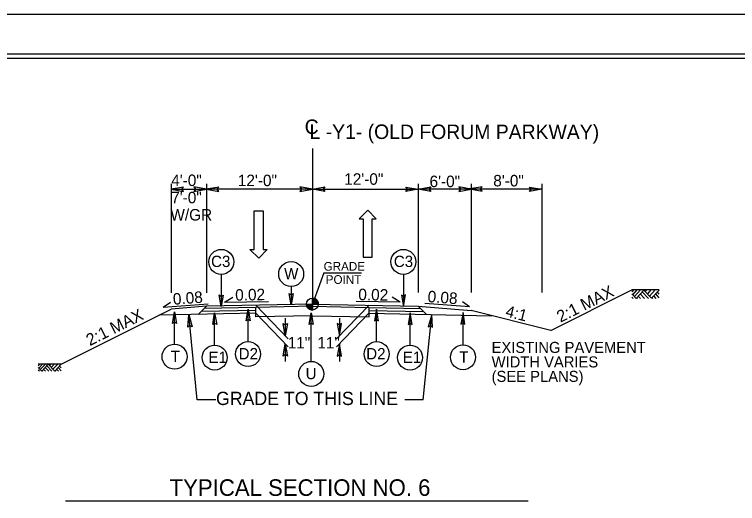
# Model space of a CAD drawing. Extents: x 1904401 to 1905163, y 193929 to 194736.
# Drawn here: x 1904832.2 to 1904914.1, y 194419 to 194474.3 of the extents above; entities that cross this region are included whole.
import ezdxf

# ---------------------------------------------------------------- set-up
doc = ezdxf.new("R2010")
doc.units = 0
for name, color, linetype in [('Old_Level_1', 7, 'Continuous'), ('Old_Level_11', 7, 'Continuous'), ('Old_Level_20', 7, 'Continuous'), ('Old_Level_3', 7, 'Continuous'), ('Prop Dimension Text', 7, 'Continuous'), ('Prop Lane Arrow CELL', 7, 'Continuous'), ('Sheet Cutting Line CELL', 7, 'Continuous'), ('Sheet Plot Border Inside CELL', 7, 'Continuous'), ('Sheet Plot Border Outside CELL', 7, 'Continuous'), ('Sheet Typical CELL', 7, 'Continuous'), ('Typical Arrow Superelevation CELL', 7, 'Continuous'), ('Typical Berm CELL', 7, 'Continuous'), ('Typical Hinge Slope Arterial CELL', 7, 'Continuous'), ('Typical Hinge Slope Interstate CELL', 7, 'Continuous'), ('Typical Terminator CELL', 7, 'Continuous'), ('Typical Text Centerline CELL', 7, 'Continuous')]:
    doc.layers.add(name, color=color, linetype=linetype)

# ---------------------------------------------------------------- blocks, each defined once
blk = doc.blocks.new('TERMINATOR')
at = {"layer": 'Typical Terminator CELL'}
blk.add_lwpolyline([(-0.469, 0.081), (0, 0), (-0.471, -0.083), (-0.411, 0)], close=True, dxfattribs=at)

msp = doc.modelspace()

# ---------------------------------------------------------------- linework, layer by layer
at = {"layer": 'Old_Level_1'}
for p, q in [((1904865.274, 194441.55), (1904865.949, 194441.55)), ((1904865.948, 194440.875), (1904865.949, 194441.55)), ((1904865.949, 194441.55), (1904865.948, 194440.875)), ((1904865.949, 194441.55), (1904865.949, 194442.225)), ((1904866.624, 194441.55), (1904865.949, 194441.55)), ((1904859.529, 194441.422), (1904863.203, 194437.626)), ((1904872.37, 194441.422), (1904868.696, 194437.626)), ((1904859.547, 194440.505), (1904863.203, 194436.729)), ((1904862.887, 194439.952), (1904862.887, 194437.952)), ((1904872.352, 194440.505), (1904868.696, 194436.729)), ((1904869.012, 194439.952), (1904869.012, 194437.952)), ((1904862.882, 194437.06), (1904862.882, 194435.06)), ((1904869.017, 194437.06), (1904869.017, 194435.06)), ((1904835.067, 194434.751), (1904834.897, 194434.567)), ((1904835.301, 194433.954), (1904834.897, 194434.389)), ((1904835.387, 194434.75), (1904834.973, 194434.306)), ((1904835.72, 194434.751), (1904835.14, 194434.128)), ((1904836.042, 194434.749), (1904835.301, 194433.954)), ((1904835.727, 194433.946), (1904835.51, 194434.178)), ((1904836.093, 194433.946), (1904835.693, 194434.374)), ((1904836.463, 194433.946), (1904835.877, 194434.574)), ((1904836.773, 194433.963), (1904836.042, 194434.749)), ((1904836.306, 194434.75), (1904836.173, 194434.608)), ((1904836.707, 194434.75), (1904836.375, 194434.391)), ((1904837.106, 194434.751), (1904836.573, 194434.177)), ((1904837.497, 194434.742), (1904836.773, 194433.963)), ((1904837.209, 194433.946), (1904836.982, 194434.189)), ((1904837.497, 194434.008), (1904837.155, 194434.374)), ((1904837.497, 194434.341), (1904837.311, 194434.541)), ((1904835.031, 194433.946), (1904834.897, 194434.089)), ((1904835.432, 194433.946), (1904835.363, 194434.019)), ((1904836.898, 194433.945), (1904836.827, 194434.021)), ((1904837.991, 194419.297), (1904890.384, 194419.297))]:
    msp.add_line(p, q, dxfattribs=at)
for points in [[(1904865.277, 194441.55), (1904865.277, 194441.477)], [(1904865.291, 194441.55), (1904865.291, 194441.397)], [(1904865.304, 194441.55), (1904865.304, 194441.349)], [(1904865.318, 194441.55), (1904865.318, 194441.309)], [(1904865.331, 194441.55), (1904865.331, 194441.277)], [(1904865.345, 194441.55), (1904865.345, 194441.249)], [(1904865.358, 194441.55), (1904865.358, 194441.223)], [(1904865.372, 194441.55), (1904865.372, 194441.199)], [(1904865.385, 194441.55), (1904865.385, 194441.178)], [(1904865.399, 194441.55), (1904865.399, 194441.159)], [(1904865.412, 194441.55), (1904865.412, 194441.141)], [(1904865.426, 194441.55), (1904865.426, 194441.124)], [(1904865.439, 194441.55), (1904865.439, 194441.108)], [(1904865.453, 194441.55), (1904865.453, 194441.093)], [(1904865.466, 194441.55), (1904865.466, 194441.078)], [(1904865.48, 194441.55), (1904865.48, 194441.064)], [(1904865.493, 194441.55), (1904865.493, 194441.052)], [(1904865.507, 194441.55), (1904865.507, 194441.04)], [(1904865.52, 194441.55), (1904865.52, 194441.028)], [(1904865.534, 194441.55), (1904865.534, 194441.018)], [(1904865.547, 194441.55), (1904865.547, 194441.007)], [(1904865.561, 194441.55), (1904865.561, 194440.998)], [(1904865.574, 194441.55), (1904865.574, 194440.989)], [(1904865.588, 194441.55), (1904865.588, 194440.98)], [(1904865.601, 194441.55), (1904865.601, 194440.971)], [(1904865.615, 194441.55), (1904865.615, 194440.964)], [(1904865.628, 194441.55), (1904865.628, 194440.956)], [(1904865.642, 194441.55), (1904865.642, 194440.949)], [(1904865.655, 194441.55), (1904865.655, 194440.943)], [(1904865.669, 194441.55), (1904865.669, 194440.937)], [(1904865.682, 194441.55), (1904865.682, 194440.931)], [(1904865.696, 194441.55), (1904865.696, 194440.925)], [(1904865.709, 194441.55), (1904865.709, 194440.919)], [(1904865.723, 194441.55), (1904865.723, 194440.914)], [(1904865.736, 194441.55), (1904865.736, 194440.91)], [(1904865.75, 194441.55), (1904865.75, 194440.905)], [(1904865.763, 194441.55), (1904865.763, 194440.902)], [(1904865.777, 194441.55), (1904865.777, 194440.898)], [(1904865.79, 194441.55), (1904865.79, 194440.895)], [(1904865.804, 194441.55), (1904865.804, 194440.892)], [(1904865.817, 194441.55), (1904865.817, 194440.889)], [(1904865.831, 194441.55), (1904865.831, 194440.886)], [(1904865.844, 194441.55), (1904865.844, 194440.884)], [(1904865.858, 194441.55), (1904865.858, 194440.881)], [(1904865.871, 194441.55), (1904865.871, 194440.88)], [(1904865.885, 194441.55), (1904865.885, 194440.878)], [(1904865.898, 194441.55), (1904865.898, 194440.877)], [(1904865.912, 194441.55), (1904865.912, 194440.877)], [(1904865.925, 194441.55), (1904865.925, 194440.875)], [(1904865.939, 194441.55), (1904865.939, 194440.875), (1904865.939, 194440.875)], [(1904865.955, 194442.225), (1904865.955, 194442.225), (1904865.955, 194441.55)], [(1904865.969, 194442.225), (1904865.969, 194441.55)], [(1904865.982, 194442.224), (1904865.982, 194441.55)], [(1904865.996, 194442.224), (1904865.996, 194441.55)], [(1904866.009, 194442.222), (1904866.009, 194441.55)], [(1904866.023, 194442.221), (1904866.023, 194441.55)], [(1904866.036, 194442.219), (1904866.036, 194441.55)], [(1904866.05, 194442.218), (1904866.05, 194441.55)], [(1904866.063, 194442.216), (1904866.063, 194441.55)], [(1904866.077, 194442.213), (1904866.077, 194441.55)], [(1904866.09, 194442.21), (1904866.09, 194441.55)], [(1904866.104, 194442.207), (1904866.104, 194441.55)], [(1904866.117, 194442.204), (1904866.117, 194441.55)], [(1904866.131, 194442.2), (1904866.131, 194441.55)], [(1904866.144, 194442.197), (1904866.144, 194441.55)], [(1904866.158, 194442.192), (1904866.158, 194441.55)], [(1904866.171, 194442.188), (1904866.171, 194441.55)], [(1904866.185, 194442.183), (1904866.185, 194441.55)], [(1904866.198, 194442.177), (1904866.198, 194441.55)], [(1904866.212, 194442.171), (1904866.212, 194441.55)], [(1904866.225, 194442.165), (1904866.225, 194441.55)], [(1904866.239, 194442.159), (1904866.239, 194441.55)], [(1904866.252, 194442.153), (1904866.252, 194441.55)], [(1904866.266, 194442.146), (1904866.266, 194441.55)], [(1904866.279, 194442.138), (1904866.279, 194441.55)], [(1904866.293, 194442.131), (1904866.293, 194441.55)], [(1904866.306, 194442.123), (1904866.306, 194441.55)], [(1904866.32, 194442.114), (1904866.32, 194441.55)], [(1904866.333, 194442.105), (1904866.333, 194441.55)], [(1904866.347, 194442.095), (1904866.347, 194441.55)], [(1904866.36, 194442.086), (1904866.36, 194441.55)], [(1904866.374, 194442.075), (1904866.374, 194441.55)], [(1904866.387, 194442.063), (1904866.387, 194441.55)], [(1904866.401, 194442.051), (1904866.401, 194441.55)], [(1904866.414, 194442.039), (1904866.414, 194441.55)], [(1904866.428, 194442.026), (1904866.428, 194441.55)], [(1904866.441, 194442.012), (1904866.441, 194441.55)], [(1904866.455, 194441.997), (1904866.455, 194441.55)], [(1904866.468, 194441.981), (1904866.468, 194441.55)], [(1904866.482, 194441.964), (1904866.482, 194441.55)], [(1904866.495, 194441.946), (1904866.495, 194441.55)], [(1904866.509, 194441.927), (1904866.509, 194441.55)], [(1904866.522, 194441.906), (1904866.522, 194441.55)], [(1904866.536, 194441.883), (1904866.536, 194441.55)], [(1904866.549, 194441.859), (1904866.549, 194441.55)], [(1904866.563, 194441.831), (1904866.563, 194441.55)], [(1904866.576, 194441.799), (1904866.576, 194441.55)], [(1904866.59, 194441.762), (1904866.59, 194441.55)], [(1904866.603, 194441.715), (1904866.603, 194441.55)], [(1904866.617, 194441.646), (1904866.617, 194441.55)], [(1904837.497, 194434.751), (1904834.897, 194434.75)]]:
    msp.add_lwpolyline(points, dxfattribs=at)
msp.add_circle((1904865.949, 194441.55), 0.675, dxfattribs=at)
for start, end in [(179.99048, 269.99048), (359.99048, 89.99048)]:
    msp.add_arc((1904865.949, 194441.55), 0.675, start, end, dxfattribs=at)
at = {"layer": 'Old_Level_11'}
for p, q in [((1904855.636, 194444.918), (1904855.636, 194441.264)), ((1904876.263, 194444.918), (1904876.263, 194441.264)), ((1904863.549, 194443.537), (1904863.549, 194441.449)), ((1904858.667, 194437.304), (1904858.667, 194440.959)), ((1904873.231, 194437.304), (1904873.231, 194440.959)), ((1904850.339, 194437.012), (1904850.339, 194440.666)), ((1904854.885, 194436.903), (1904854.885, 194440.557)), ((1904865.819, 194435.062), (1904865.819, 194440.552)), ((1904877.014, 194436.903), (1904877.014, 194440.557)), ((1904883.01, 194436.942), (1904883.01, 194440.596))]:
    msp.add_line(p, q, dxfattribs=at)
for points in [[(1904855.861, 194442.573), (1904855.636, 194441.264), (1904855.403, 194442.58), (1904855.636, 194442.413)], [(1904863.774, 194442.758), (1904863.549, 194441.449), (1904863.316, 194442.765), (1904863.549, 194442.598)], [(1904876.038, 194442.573), (1904876.263, 194441.264), (1904876.496, 194442.58), (1904876.263, 194442.413)], [(1904858.442, 194439.649), (1904858.667, 194440.959), (1904858.9, 194439.643), (1904858.667, 194439.81)], [(1904873.457, 194439.649), (1904873.231, 194440.959), (1904872.998, 194439.643), (1904873.231, 194439.81)], [(1904850.114, 194439.357), (1904850.339, 194440.666), (1904850.572, 194439.35), (1904850.339, 194439.517)], [(1904854.66, 194439.248), (1904854.885, 194440.557), (1904855.118, 194439.241), (1904854.885, 194439.408)], [(1904865.593, 194439.242), (1904865.819, 194440.552), (1904866.052, 194439.235), (1904865.819, 194439.403)], [(1904877.239, 194439.248), (1904877.014, 194440.557), (1904876.781, 194439.241), (1904877.014, 194439.408)], [(1904883.235, 194439.287), (1904883.01, 194440.596), (1904882.777, 194439.28), (1904883.01, 194439.447)]]:
    msp.add_lwpolyline(points, close=True, dxfattribs=at)
for centre in [(1904855.636, 194446.332), (1904876.263, 194446.332), (1904863.549, 194444.952), (1904850.339, 194435.598), (1904854.885, 194435.489), (1904858.667, 194435.89), (1904873.231, 194435.89), (1904877.014, 194435.489), (1904883.01, 194435.528), (1904865.819, 194433.648)]:
    msp.add_circle(centre, 1.414, dxfattribs=at)
at = {"layer": 'Old_Level_3'}
for q in [(1904865.949, 194441.55), (1904871.496, 194445.093)]:
    msp.add_line((1904867.239, 194445.093), q, dxfattribs=at)
at = {"layer": 'Prop Lane Arrow CELL'}
for p, q in [((1904853.949, 194455.156), (1904853.949, 194442.822)), ((1904877.949, 194455.156), (1904877.949, 194442.845)), ((1904849.949, 194454.556), (1904853.949, 194454.556)), ((1904865.949, 194454.556), (1904853.949, 194454.556)), ((1904865.949, 194454.556), (1904877.949, 194454.556)), ((1904891.949, 194454.556), (1904877.949, 194454.556)), ((1904872.229, 194452.184), (1904871.233, 194451.204)), ((1904873.194, 194451.204), (1904872.229, 194452.184)), ((1904859.343, 194452.09), (1904860.371, 194452.09)), ((1904859.343, 194447.733), (1904859.343, 194452.09)), ((1904860.371, 194452.09), (1904860.371, 194447.733)), ((1904871.233, 194451.204), (1904871.7, 194451.204)), ((1904871.7, 194451.204), (1904871.7, 194446.847)), ((1904872.727, 194446.847), (1904872.727, 194451.204)), ((1904872.727, 194451.204), (1904873.194, 194451.204)), ((1904859.873, 194446.752), (1904858.877, 194447.733)), ((1904858.877, 194447.733), (1904859.343, 194447.733)), ((1904860.837, 194447.733), (1904859.873, 194446.752)), ((1904860.371, 194447.733), (1904860.837, 194447.733)), ((1904871.7, 194446.847), (1904872.727, 194446.847)), ((1904902.325, 194443.146), (1904902.121, 194442.927)), ((1904902.282, 194442.18), (1904902.121, 194442.352)), ((1904902.606, 194442.19), (1904902.122, 194442.712)), ((1904902.71, 194443.146), (1904902.213, 194442.613)), ((1904903.109, 194443.146), (1904902.413, 194442.399)), ((1904903.496, 194443.145), (1904902.606, 194442.19)), ((1904903.117, 194442.18), (1904902.857, 194442.46)), ((1904903.557, 194442.18), (1904903.077, 194442.695)), ((1904904.001, 194442.18), (1904903.297, 194442.934)), ((1904904.373, 194442.202), (1904903.496, 194443.145)), ((1904903.812, 194443.146), (1904903.653, 194442.975)), ((1904904.295, 194443.146), (1904903.895, 194442.715)), ((1904904.772, 194443.146), (1904904.133, 194442.459)), ((1904905.242, 194443.137), (1904904.373, 194442.202)), ((1904904.896, 194442.18), (1904904.624, 194442.472)), ((1904905.242, 194442.256), (1904904.831, 194442.695)), ((1904905.242, 194442.655), (1904905.018, 194442.895)), ((1904865.949, 194441.55), (1904853.949, 194441.31)), ((1904865.949, 194441.55), (1904877.949, 194441.31)), ((1904902.764, 194442.18), (1904902.681, 194442.269)), ((1904904.523, 194442.18), (1904904.437, 194442.271)), ((1904853.949, 194441.31), (1904849.949, 194440.977)), ((1904853.014, 194440.375), (1904853.949, 194441.31)), ((1904859.547, 194440.839), (1904853.354, 194440.715)), ((1904859.547, 194441.172), (1904853.694, 194441.055)), ((1904872.368, 194441.172), (1904878.205, 194441.055)), ((1904872.368, 194440.838), (1904878.545, 194440.715)), ((1904878.885, 194440.375), (1904877.949, 194441.31)), ((1904877.949, 194441.31), (1904883.949, 194440.81)), ((1904859.547, 194440.505), (1904848.567, 194440.286)), ((1904852.922, 194430.73), (1904851.948, 194440.353)), ((1904872.368, 194440.505), (1904886.283, 194440.227)), ((1904878.5, 194430.73), (1904879.474, 194440.363)), ((1904855.001, 194430.73), (1904852.922, 194430.73)), ((1904878.5, 194430.73), (1904876.421, 194430.73))]:
    msp.add_line(p, q, dxfattribs=at)
msp.add_lwpolyline([(1904905.242, 194443.146), (1904902.122, 194443.146)], dxfattribs=at)
at = {"layer": 'Sheet Cutting Line CELL'}
msp.add_line((1905047.492, 194474.335), (1904710.692, 194474.335), dxfattribs=at)
at = {"layer": 'Sheet Plot Border Inside CELL'}
msp.add_lwpolyline([(1905046.592, 194469.845), (1904713.292, 194469.845), (1904713.292, 194258.825), (1905046.592, 194258.825)], close=True, dxfattribs=at)
at = {"layer": 'Sheet Plot Border Outside CELL'}
msp.add_lwpolyline([(1905047.492, 194474.335), (1904710.692, 194474.335), (1904710.692, 194254.335), (1905047.492, 194254.335)], close=True, dxfattribs=at)
at = {"layer": 'Sheet Typical CELL'}
msp.add_lwpolyline([(1905044.092, 194469.335), (1904744.092, 194469.335), (1904744.092, 194259.335), (1905044.092, 194259.335)], close=True, dxfattribs=at)
at = {"layer": 'Typical Arrow Superelevation CELL'}
for p, q in [((1904849.071, 194441.202), (1904849.898, 194441.764)), ((1904849.071, 194441.202), (1904854.152, 194441.575)), ((1904855.986, 194441.76), (1904856.926, 194442.328)), ((1904855.986, 194441.76), (1904860.997, 194441.86)), ((1904875.912, 194441.76), (1904870.902, 194441.86)), ((1904875.912, 194441.76), (1904874.973, 194442.328)), ((1904883.763, 194441.249), (1904878.682, 194441.622)), ((1904883.763, 194441.249), (1904882.936, 194441.811))]:
    msp.add_line(p, q, dxfattribs=at)
at = {"layer": 'Typical Berm CELL'}
for p, q in [((1904849.949, 194455.156), (1904849.949, 194442.822)), ((1904883.949, 194455.156), (1904883.949, 194442.845)), ((1904891.949, 194455.156), (1904891.949, 194442.845)), ((1904865.965, 194441.3), (1904859.547, 194441.172)), ((1904859.547, 194440.106), (1904859.547, 194441.172)), ((1904865.949, 194441.3), (1904872.368, 194441.172)), ((1904872.368, 194440.107), (1904872.368, 194441.172)), ((1904865.965, 194440.235), (1904859.547, 194440.106)), ((1904865.949, 194440.235), (1904872.368, 194440.107))]:
    msp.add_line(p, q, dxfattribs=at)
at = {"layer": 'Typical Hinge Slope Arterial CELL'}
for p, q in [((1904892.949, 194438.56), (1904902.122, 194443.146)), ((1904837.497, 194434.751), (1904849.949, 194440.977))]:
    msp.add_line(p, q, dxfattribs=at)
at = {"layer": 'Typical Hinge Slope Interstate CELL'}
msp.add_line((1904892.949, 194438.56), (1904883.949, 194440.81), dxfattribs=at)
at = {"layer": 'Typical Terminator CELL'}
for points in [[(1904851.355, 194454.798), (1904849.949, 194454.556), (1904851.363, 194454.306), (1904851.184, 194454.556)], [(1904852.543, 194454.314), (1904853.949, 194454.556), (1904852.536, 194454.806), (1904852.715, 194454.556)], [(1904855.355, 194454.798), (1904853.949, 194454.556), (1904855.363, 194454.306), (1904855.184, 194454.556)], [(1904864.543, 194454.314), (1904865.949, 194454.556), (1904864.536, 194454.806), (1904864.715, 194454.556)], [(1904867.355, 194454.314), (1904865.949, 194454.556), (1904867.363, 194454.806), (1904867.184, 194454.556)], [(1904876.543, 194454.798), (1904877.949, 194454.556), (1904876.536, 194454.306), (1904876.715, 194454.556)], [(1904879.355, 194454.314), (1904877.949, 194454.556), (1904879.363, 194454.806), (1904879.184, 194454.556)], [(1904882.543, 194454.314), (1904883.949, 194454.556), (1904882.536, 194454.806), (1904882.715, 194454.556)], [(1904885.181, 194454.829), (1904883.775, 194454.587), (1904885.189, 194454.337), (1904885.009, 194454.587)], [(1904890.543, 194454.798), (1904891.949, 194454.556), (1904890.536, 194454.306), (1904890.715, 194454.556)], [(1904851.861, 194438.929), (1904851.948, 194440.353), (1904852.351, 194438.975), (1904852.083, 194439.127)], [(1904879.561, 194438.939), (1904879.474, 194440.363), (1904879.071, 194438.985), (1904879.339, 194439.136)]]:
    msp.add_lwpolyline(points, close=True, dxfattribs=at)
at = {"layer": 'Typical Text Centerline CELL'}
msp.add_line((1904865.949, 194459.157), (1904865.949, 194441.55), dxfattribs=at)

# ---------------------------------------------------------------- block references
at = {"layer": 'Old_Level_1', "xscale": 3}
for p, yscale, rotation in [((1904862.887, 194437.952), 3, -90), ((1904869.012, 194437.952), -3, -90.00000000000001), ((1904862.882, 194437.06), 3, 90), ((1904869.017, 194437.06), -3, 90)]:
    msp.add_blockref('TERMINATOR', p, dxfattribs=dict(at, yscale=yscale, rotation=rotation))

# ---------------------------------------------------------------- texts
at = {"layer": 'Old_Level_1'}
for s, p in [('4\'-0" ', (1904849.964, 194454.912)), ('6\'-0"', (1904879.222, 194454.791)), ('7\'-0"', (1904849.964, 194452.962)), ('W/GR', (1904849.87, 194451.012))]:
    msp.add_text(s, height=1.3, dxfattribs=at).set_placement(p)
at = {"layer": 'Old_Level_11'}
for s, p in [('GRADE', (1904867.229, 194445.33)), ('POINT', (1904867.466, 194443.839))]:
    msp.add_text(s, height=0.984, dxfattribs=at).set_placement(p)
at = {"layer": 'Old_Level_20'}
for s, height, p in [('C3', 1.2792, (1904854.479, 194445.747)), ('C3', 1.2792, (1904875.178, 194445.747)), ('W', 1.279, (1904862.754, 194444.354)), ('11"', 1.3, (1904863.158, 194436.525)), ('11"', 1.3, (1904866.514, 194436.525)), ('T', 1.279, (1904849.903, 194435.001)), ('E1', 1.2792, (1904854.177, 194434.891)), ('D2', 1.2792, (1904857.603, 194435.293)), ('D2', 1.2792, (1904872.048, 194435.293)), ('E1', 1.2792, (1904876.187, 194434.891)), ('T', 1.279, (1904882.581, 194434.93)), ('U', 1.279, (1904865.186, 194433.051))]:
    msp.add_text(s, height=height, dxfattribs=at).set_placement(p)
at = {"layer": 'Prop Dimension Text'}
for rotation, p in [(1.1462, (1904857.222, 194441.933)), (358.8538, (1904871.144, 194442.003))]:
    msp.add_text('0.02', height=1.3, rotation=rotation, dxfattribs=at).set_placement(p)
at = {"layer": 'Prop Lane Arrow CELL'}
for s, height, p in [('12\'-0"', 1.3, (1904869.559, 194455.057)), ('12\'-0"', 1.3, (1904857.51, 194454.9)), ('8\'-0"', 1.3, (1904886.438, 194454.871)), ('EXISTING PAVEMENT', 1.25, (1904886.249, 194436.021)), ('WIDTH VARIES', 1.25, (1904886.249, 194434.382)), ('(SEE PLANS)', 1.25, (1904886.249, 194432.744)), ('TYPICAL SECTION NO. 6', 1.875, (1904849.786, 194419.841))]:
    msp.add_text(s, height=height, dxfattribs=at).set_placement(p)
for s, height, rotation, p in [('0.08', 1.3, 4.19823, (1904850.204, 194441.466)), ('0.08', 1.3, 355.80177, (1904878.967, 194441.781)), ('GRADE TO THIS LINE', 1.5, 0.00016, (1904855.036, 194430.123))]:
    msp.add_text(s, height=height, rotation=rotation, dxfattribs=at).set_placement(p)
at = {"layer": 'Typical Hinge Slope Arterial CELL'}
for p in [(1904894.046, 194439.426), (1904840.75, 194436.782)]:
    msp.add_text('2:1 MAX', height=1.35, rotation=26.56505, dxfattribs=at).set_placement(p)
at = {"layer": 'Typical Hinge Slope Interstate CELL'}
msp.add_text('4:1', height=1.3, rotation=345.52839, dxfattribs=at).set_placement((1904887.738, 194440.175))
at = {"layer": 'Typical Text Centerline CELL'}
msp.add_text('C', height=1.64, dxfattribs=at).set_placement((1904865.081, 194460.808))
msp.add_text('L -Y1- (OLD FORUM PARKWAY) ', height=1.64109, rotation=359.9469, dxfattribs=at).set_placement((1904865.627, 194460.248))

doc.saveas('drawing.dxf')
